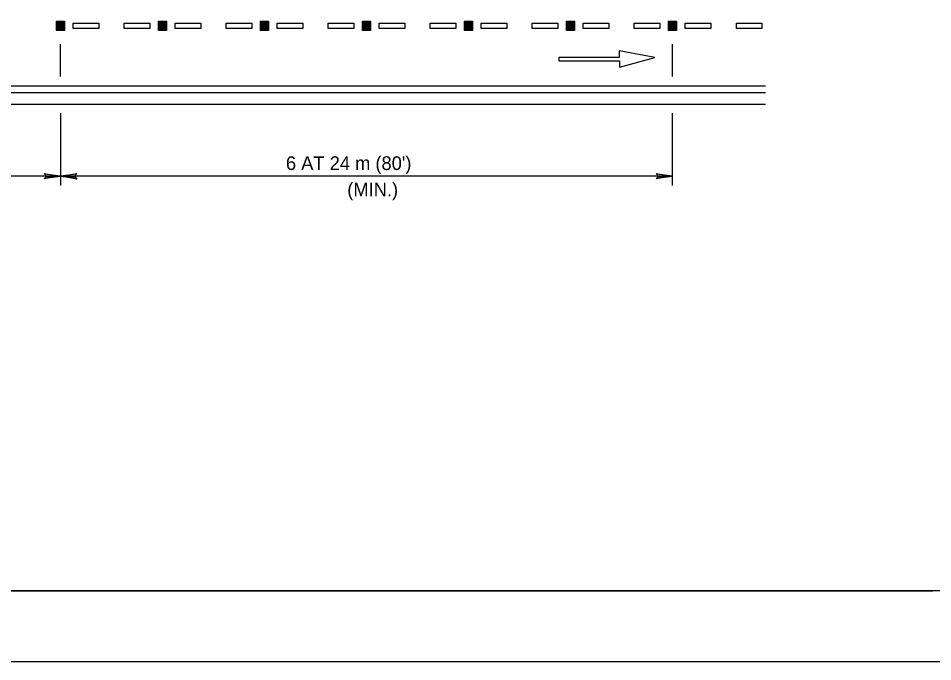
# Model space of a CAD drawing. Extents: x 639362 to 641108, y 298458 to 299646.
# Drawn here: x 639788.7 to 639989.3, y 298457.6 to 298598.6 of the extents above; entities that cross this region are included whole.
import ezdxf

# ---------------------------------------------------------------- set-up
doc = ezdxf.new("R2010")
doc.units = 0
for name, color, linetype in [('1', 7, 'Continuous'), ('2', 7, 'Continuous'), ('3', 7, 'Continuous'), ('PLT-BNDY', 7, 'Continuous')]:
    doc.layers.add(name, color=color, linetype=linetype)

# ---------------------------------------------------------------- blocks, each defined once
blk = doc.blocks.new('RARROW')
at = {"layer": '3'}
blk.add_lwpolyline([(-2.2695, 0.285), (-2.184875, 0.12075), (0, 0), (-2.2695, 0.285), (-2.38575, 0.384625), (0, 0), (-2.183125, -0.108), (-2.262875, -0.2705), (0, 0), (-2.38575, -0.379125), (-2.262875, -0.2705)], dxfattribs=at)

msp = doc.modelspace()

# ---------------------------------------------------------------- linework, layer by layer
at = {"layer": '1'}
for p, q in [((640189.27, 298473.19), (639403.27, 298473.19)), ((639403.27, 298473.19), (639989.27, 298473.19))]:
    msp.add_line(p, q, dxfattribs=at)
at = {"layer": '2'}
for p, q in [((639797.12, 298598), (639798.89, 298598)), ((639797.12, 298595.96), (639797.12, 298598)), ((639797.29, 298597.82), (639798.71, 298597.82)), ((639797.29, 298596.14), (639797.29, 298597.82)), ((639797.47, 298597.64), (639798.54, 298597.64)), ((639797.47, 298596.31), (639797.47, 298597.64)), ((639797.65, 298596.49), (639797.65, 298597.47)), ((639797.65, 298597.47), (639798.36, 298597.47)), ((639797.83, 298597.29), (639798.18, 298597.29)), ((639797.83, 298596.67), (639797.83, 298597.29)), ((639798, 298597.11), (639798, 298596.85)), ((639798.18, 298597.29), (639798.18, 298596.67)), ((639798.36, 298597.47), (639798.36, 298596.49)), ((639798.54, 298597.64), (639798.54, 298596.31)), ((639798.71, 298597.82), (639798.71, 298596.14)), ((639798.89, 298598), (639798.89, 298595.96)), ((639800.79, 298596.4), (639800.79, 298597.6)), ((639800.79, 298597.6), (639806.38, 298597.6)), ((639806.38, 298597.6), (639806.38, 298596.4)), ((639811.98, 298596.4), (639811.98, 298597.6)), ((639811.98, 298597.6), (639817.57, 298597.6)), ((639817.57, 298597.6), (639817.57, 298596.4)), ((639819.48, 298598.02), (639821.25, 298598.02)), ((639819.48, 298595.98), (639819.48, 298598.02)), ((639819.66, 298597.84), (639821.08, 298597.84)), ((639819.66, 298596.15), (639819.66, 298597.84)), ((639819.83, 298597.66), (639820.9, 298597.66)), ((639819.83, 298596.33), (639819.83, 298597.66)), ((639820.01, 298596.51), (639820.01, 298597.48)), ((639820.01, 298597.48), (639820.72, 298597.48)), ((639820.19, 298597.31), (639820.54, 298597.31)), ((639820.19, 298596.69), (639820.19, 298597.31)), ((639820.36, 298597.13), (639820.36, 298596.86)), ((639820.54, 298597.31), (639820.54, 298596.69)), ((639820.72, 298597.48), (639820.72, 298596.51)), ((639820.9, 298597.66), (639820.9, 298596.33)), ((639821.08, 298597.84), (639821.08, 298596.15)), ((639821.25, 298598.02), (639821.25, 298595.98)), ((639823.16, 298596.4), (639823.16, 298597.6)), ((639823.16, 298597.6), (639828.75, 298597.6)), ((639828.75, 298597.6), (639828.75, 298596.4)), ((639834.34, 298596.4), (639834.34, 298597.6)), ((639834.34, 298597.6), (639839.94, 298597.6)), ((639839.94, 298597.6), (639839.94, 298596.4)), ((639841.85, 298598.02), (639843.62, 298598.02)), ((639841.85, 298595.98), (639841.85, 298598.02)), ((639842.02, 298597.84), (639843.44, 298597.84)), ((639842.02, 298596.15), (639842.02, 298597.84)), ((639842.2, 298597.66), (639843.27, 298597.66)), ((639842.2, 298596.33), (639842.2, 298597.66)), ((639842.38, 298596.51), (639842.38, 298597.48)), ((639842.38, 298597.48), (639843.09, 298597.48)), ((639842.56, 298597.31), (639842.91, 298597.31)), ((639842.56, 298596.69), (639842.56, 298597.31)), ((639842.73, 298597.13), (639842.73, 298596.86)), ((639842.91, 298597.31), (639842.91, 298596.69)), ((639843.09, 298597.48), (639843.09, 298596.51)), ((639843.27, 298597.66), (639843.27, 298596.33)), ((639843.44, 298597.84), (639843.44, 298596.15)), ((639843.62, 298598.02), (639843.62, 298595.98)), ((639845.53, 298596.4), (639845.53, 298597.6)), ((639845.53, 298597.6), (639851.12, 298597.6)), ((639851.12, 298597.6), (639851.12, 298596.4)), ((639856.71, 298596.4), (639856.71, 298597.6)), ((639856.71, 298597.6), (639862.3, 298597.6)), ((639862.3, 298597.6), (639862.3, 298596.4)), ((639864.21, 298598.02), (639865.99, 298598.02)), ((639864.21, 298595.98), (639864.21, 298598.02)), ((639864.39, 298597.84), (639865.81, 298597.84)), ((639864.39, 298596.15), (639864.39, 298597.84)), ((639864.57, 298597.66), (639865.63, 298597.66)), ((639864.57, 298596.33), (639864.57, 298597.66)), ((639864.75, 298596.51), (639864.75, 298597.48)), ((639864.75, 298597.48), (639865.46, 298597.48)), ((639864.92, 298597.31), (639865.28, 298597.31)), ((639864.92, 298596.69), (639864.92, 298597.31)), ((639865.1, 298597.13), (639865.1, 298596.86)), ((639865.28, 298597.31), (639865.28, 298596.69)), ((639865.46, 298597.48), (639865.46, 298596.51)), ((639865.63, 298597.66), (639865.63, 298596.33)), ((639865.81, 298597.84), (639865.81, 298596.15)), ((639865.99, 298598.02), (639865.99, 298595.98)), ((639867.89, 298596.4), (639867.89, 298597.6)), ((639867.89, 298597.6), (639873.49, 298597.6)), ((639873.49, 298597.6), (639873.49, 298596.4)), ((639879.08, 298596.4), (639879.08, 298597.6)), ((639879.08, 298597.6), (639884.67, 298597.6)), ((639884.67, 298597.6), (639884.67, 298596.4)), ((639886.58, 298598.02), (639888.36, 298598.02)), ((639886.58, 298595.98), (639886.58, 298598.02)), ((639886.76, 298597.84), (639888.18, 298597.84)), ((639886.76, 298596.15), (639886.76, 298597.84)), ((639886.94, 298597.66), (639888, 298597.66)), ((639886.94, 298596.33), (639886.94, 298597.66)), ((639887.11, 298596.51), (639887.11, 298597.48)), ((639887.11, 298597.48), (639887.82, 298597.48)), ((639887.29, 298597.31), (639887.65, 298597.31)), ((639887.29, 298596.69), (639887.29, 298597.31)), ((639887.47, 298597.13), (639887.47, 298596.86)), ((639887.65, 298597.31), (639887.65, 298596.69)), ((639887.82, 298597.48), (639887.82, 298596.51)), ((639888, 298597.66), (639888, 298596.33)), ((639888.18, 298597.84), (639888.18, 298596.15)), ((639888.36, 298598.02), (639888.36, 298595.98)), ((639890.26, 298596.4), (639890.26, 298597.6)), ((639890.26, 298597.6), (639895.85, 298597.6)), ((639895.85, 298597.6), (639895.85, 298596.4)), ((639901.45, 298596.4), (639901.45, 298597.6)), ((639901.45, 298597.6), (639907.04, 298597.6)), ((639907.04, 298597.6), (639907.04, 298596.4)), ((639908.95, 298598.02), (639910.72, 298598.02)), ((639908.95, 298595.98), (639908.95, 298598.02)), ((639909.13, 298597.84), (639910.55, 298597.84)), ((639909.13, 298596.15), (639909.13, 298597.84)), ((639909.3, 298597.66), (639910.37, 298597.66)), ((639909.3, 298596.33), (639909.3, 298597.66)), ((639909.48, 298596.51), (639909.48, 298597.48)), ((639909.48, 298597.48), (639910.19, 298597.48)), ((639909.66, 298597.31), (639910.01, 298597.31)), ((639909.66, 298596.69), (639909.66, 298597.31)), ((639909.83, 298597.13), (639909.83, 298596.86)), ((639910.01, 298597.31), (639910.01, 298596.69)), ((639910.19, 298597.48), (639910.19, 298596.51)), ((639910.37, 298597.66), (639910.37, 298596.33)), ((639910.55, 298597.84), (639910.55, 298596.15)), ((639910.72, 298598.02), (639910.72, 298595.98)), ((639912.63, 298596.4), (639912.63, 298597.6)), ((639912.63, 298597.6), (639918.22, 298597.6)), ((639918.22, 298597.6), (639918.22, 298596.4)), ((639923.81, 298596.4), (639923.81, 298597.6)), ((639923.81, 298597.6), (639929.41, 298597.6)), ((639929.41, 298597.6), (639929.41, 298596.4)), ((639931.32, 298598.02), (639933.09, 298598.02)), ((639931.32, 298595.98), (639931.32, 298598.02)), ((639931.49, 298597.84), (639932.91, 298597.84)), ((639931.49, 298596.15), (639931.49, 298597.84)), ((639931.67, 298597.66), (639932.74, 298597.66)), ((639931.67, 298596.33), (639931.67, 298597.66)), ((639931.85, 298596.51), (639931.85, 298597.48)), ((639931.85, 298597.48), (639932.56, 298597.48)), ((639932.03, 298597.31), (639932.38, 298597.31)), ((639932.03, 298596.69), (639932.03, 298597.31)), ((639932.2, 298597.13), (639932.2, 298596.86)), ((639932.38, 298597.31), (639932.38, 298596.69)), ((639932.56, 298597.48), (639932.56, 298596.51)), ((639932.74, 298597.66), (639932.74, 298596.33)), ((639932.91, 298597.84), (639932.91, 298596.15)), ((639933.09, 298598.02), (639933.09, 298595.98)), ((639935.01, 298596.4), (639935.01, 298597.6)), ((639935.01, 298597.6), (639940.6, 298597.6)), ((639940.6, 298597.6), (639940.6, 298596.4)), ((639946.21, 298596.4), (639946.21, 298597.6)), ((639946.21, 298597.6), (639951.8, 298597.6)), ((639951.8, 298597.6), (639951.8, 298596.4)), ((639798.89, 298595.96), (639797.12, 298595.96)), ((639798.71, 298596.14), (639797.29, 298596.14)), ((639798.54, 298596.31), (639797.47, 298596.31)), ((639798.36, 298596.49), (639797.65, 298596.49)), ((639798.18, 298596.67), (639797.83, 298596.67)), ((639806.38, 298596.4), (639800.79, 298596.4)), ((639817.57, 298596.4), (639811.98, 298596.4)), ((639821.25, 298595.98), (639819.48, 298595.98)), ((639821.08, 298596.15), (639819.66, 298596.15)), ((639820.9, 298596.33), (639819.83, 298596.33)), ((639820.72, 298596.51), (639820.01, 298596.51)), ((639820.54, 298596.69), (639820.19, 298596.69)), ((639828.75, 298596.4), (639823.16, 298596.4)), ((639839.94, 298596.4), (639834.34, 298596.4)), ((639843.62, 298595.98), (639841.85, 298595.98)), ((639843.44, 298596.15), (639842.02, 298596.15)), ((639843.27, 298596.33), (639842.2, 298596.33)), ((639843.09, 298596.51), (639842.38, 298596.51)), ((639842.91, 298596.69), (639842.56, 298596.69)), ((639851.12, 298596.4), (639845.53, 298596.4)), ((639862.3, 298596.4), (639856.71, 298596.4)), ((639865.99, 298595.98), (639864.21, 298595.98)), ((639865.81, 298596.15), (639864.39, 298596.15)), ((639865.63, 298596.33), (639864.57, 298596.33)), ((639865.46, 298596.51), (639864.75, 298596.51)), ((639865.28, 298596.69), (639864.92, 298596.69)), ((639873.49, 298596.4), (639867.89, 298596.4)), ((639884.67, 298596.4), (639879.08, 298596.4)), ((639888.36, 298595.98), (639886.58, 298595.98)), ((639888.18, 298596.15), (639886.76, 298596.15)), ((639888, 298596.33), (639886.94, 298596.33)), ((639887.82, 298596.51), (639887.11, 298596.51)), ((639887.65, 298596.69), (639887.29, 298596.69)), ((639895.85, 298596.4), (639890.26, 298596.4)), ((639907.04, 298596.4), (639901.45, 298596.4)), ((639910.72, 298595.98), (639908.95, 298595.98)), ((639910.55, 298596.15), (639909.13, 298596.15)), ((639910.37, 298596.33), (639909.3, 298596.33)), ((639910.19, 298596.51), (639909.48, 298596.51)), ((639910.01, 298596.69), (639909.66, 298596.69)), ((639918.22, 298596.4), (639912.63, 298596.4)), ((639929.41, 298596.4), (639923.81, 298596.4)), ((639933.09, 298595.98), (639931.32, 298595.98)), ((639932.91, 298596.15), (639931.49, 298596.15)), ((639932.74, 298596.33), (639931.67, 298596.33)), ((639932.56, 298596.51), (639931.85, 298596.51)), ((639932.38, 298596.69), (639932.03, 298596.69)), ((639940.6, 298596.4), (639935.01, 298596.4)), ((639951.8, 298596.4), (639946.21, 298596.4)), ((639798, 298585.85), (639798, 298593)), ((639928.31, 298590.03), (639920.5, 298591.5)), ((639920.5, 298591.5), (639920.5, 298590.06)), ((639932.2, 298585.85), (639932.2, 298593)), ((639920.5, 298590.06), (639907.26, 298590.06)), ((639907.26, 298590.06), (639907.26, 298589.35)), ((639907.26, 298589.35), (639920.58, 298589.35)), ((639920.58, 298587.91), (639928.31, 298590.03)), ((639920.58, 298589.35), (639920.58, 298587.91)), ((639431.63, 298583.85), (639951.12, 298583.85)), ((639797.99, 298583.85), (639952.64, 298583.85)), ((639431.63, 298582.35), (639951.12, 298582.35)), ((639797.99, 298582.35), (639952.64, 298582.35)), ((639431.63, 298579.85), (639951.12, 298579.85)), ((639797.99, 298579.85), (639952.64, 298579.85)), ((639798, 298577.85), (639798, 298562.02)), ((639932.2, 298562.02), (639932.2, 298577.85)), ((639798, 298564.02), (639585.52, 298564.02)), ((639932.2, 298564.02), (639798, 298564.02))]:
    msp.add_line(p, q, dxfattribs=at)
at = {"layer": 'PLT-BNDY'}
msp.add_lwpolyline([(639362.31, 299051.63), (640203.31, 299051.63), (640203.31, 298457.63), (639362.31, 298457.63)], close=True, dxfattribs=at)

# ---------------------------------------------------------------- block references
at = {"layer": '2', "xscale": 1.5089217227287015, "yscale": 1.5711553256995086}
for p in [(639798, 298564.02), (639932.2, 298564.02)]:
    msp.add_blockref('RARROW', p, dxfattribs=at)
at = {"layer": '2', "xscale": 1.5089217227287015, "yscale": 1.5711553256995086, "rotation": 180}
msp.add_blockref('RARROW', (639798, 298564.02), dxfattribs=at)

# ---------------------------------------------------------------- texts
at = {"layer": '2'}
for s, p in [("6 AT 24 m (80')", (639847.44, 298565.39)), ('(MIN.)', (639860.89, 298559.63))]:
    msp.add_text(s, height=3, dxfattribs=at).set_placement(p)

doc.saveas('drawing.dxf')
